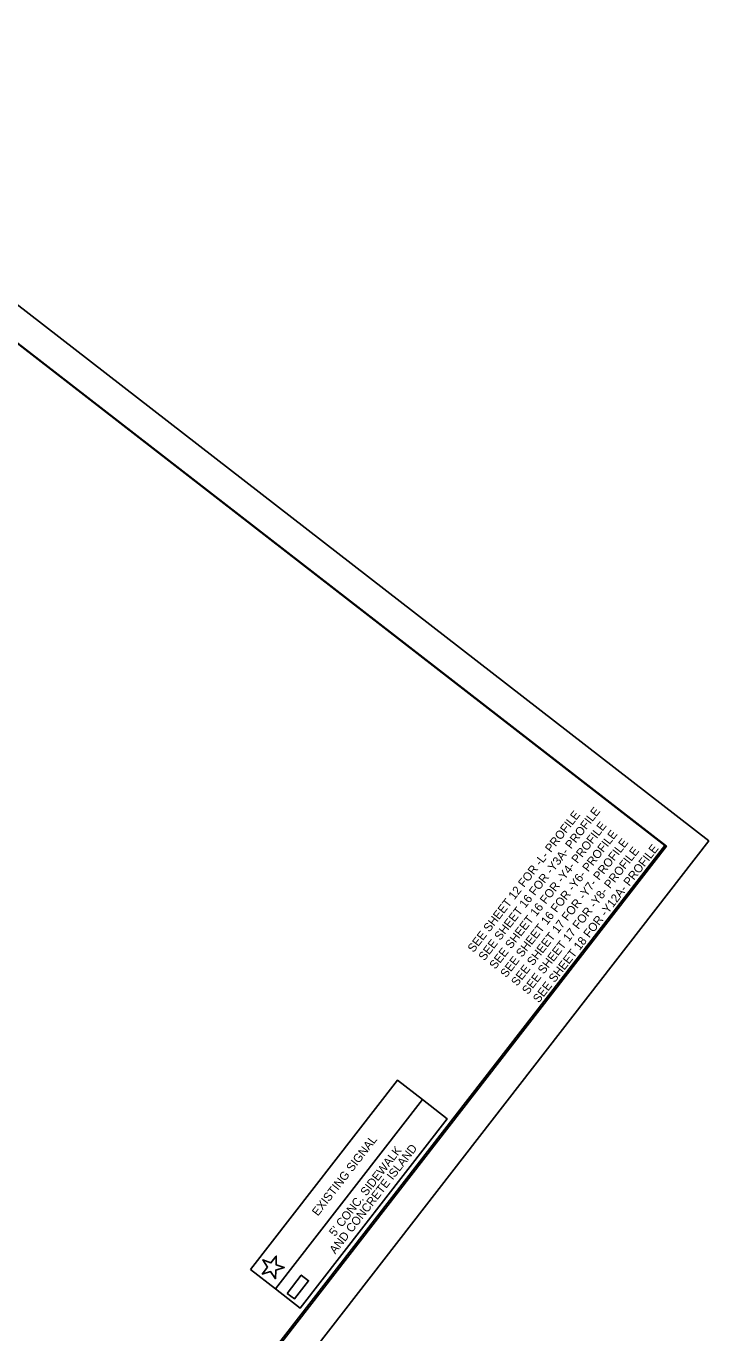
# Model space of a CAD drawing. Extents: x 2013373 to 2015284, y 444589 to 446636.
# Drawn here: x 2014719 to 2015284, y 445554 to 446636 of the extents above; entities that cross this region are included whole.
import ezdxf

# ---------------------------------------------------------------- set-up
doc = ezdxf.new("R2010")
doc.units = 0
for name, color, linetype in [('Old_Level_1', 7, 'Continuous'), ('Prop DSN Text', 7, 'Continuous'), ('Prop RDY Traffic Signal CELL', 7, 'Continuous'), ('Prop Shade Medium', 7, 'Continuous'), ('Sheet Clip Boundary CELL', 7, 'Continuous'), ('Sheet Plan And Profile CELL', 7, 'Continuous'), ('Sheet Plot Border Outside CELL', 7, 'Continuous')]:
    doc.layers.add(name, color=color, linetype=linetype)

msp = doc.modelspace()

# ---------------------------------------------------------------- linework, layer by layer
at = {"layer": 'Old_Level_1'}
for points in [[(2014904.7, 445606.9), (2015026.2, 445763.5), (2015046.8, 445747.5), (2014925.3, 445590.9)], [(2014925.3, 445590.9), (2015046.8, 445747.5), (2015067.4, 445731.5), (2014945.9, 445574.9)]]:
    msp.add_lwpolyline(points, close=True, dxfattribs=at)
at = {"layer": 'Prop RDY Traffic Signal CELL'}
msp.add_lwpolyline([(2014918.8, 445608.8), (2014914.4, 445603.1), (2014921.3, 445605.1), (2014925.4, 445599.2), (2014925.6, 445606.4), (2014932.6, 445608.4), (2014925.8, 445610.8), (2014926, 445618), (2014921.6, 445612.3), (2014914.8, 445614.8), (2014918.8, 445608.8)], dxfattribs=at)
at = {"layer": 'Prop Shade Medium'}
msp.add_lwpolyline([(2014935, 445587.1), (2014946.7, 445602.2), (2014952.7, 445597.5), (2014941, 445582.5)], close=True, dxfattribs=at)
at = {"layer": 'Sheet Clip Boundary CELL'}
msp.add_lwpolyline([(2014175.9, 446280.2), (2013513.1, 445427.6), (2013603.8, 445375.4), (2013612.4, 445329.9), (2013915.8, 445258.4), (2014042, 445083.4), (2014361.1, 444814.9), (2015247.4, 445957.7), (2014564.2, 446487.4), (2014441.6, 446328.9), (2014350.6, 446399.7), (2014226.8, 446240.6)], close=True, dxfattribs=at)
at = {"layer": 'Sheet Plan And Profile CELL'}
msp.add_lwpolyline([(2014418.9, 446600.4), (2013499.7, 445415.1), (2014329.4, 444771.6), (2015248.7, 445957)], close=True, dxfattribs=at)
at = {"layer": 'Sheet Plot Border Outside CELL'}
msp.add_lwpolyline([(2014241.9, 444618), (2015283.7, 445961.4), (2014414.5, 446635.5), (2013372.7, 445292.2)], close=True, dxfattribs=at)

# ---------------------------------------------------------------- texts
at = {"layer": 'Prop DSN Text'}
for s, p in [('SEE SHEET 12 FOR -L- PROFILE', (2015089.1, 445868.7)), ('SEE SHEET 16 FOR -Y3A- PROFILE', (2015098.1, 445861.8)), ('SEE SHEET 16 FOR -Y4- PROFILE', (2015107.1, 445854.8)), ('SEE SHEET 16 FOR -Y6- PROFILE', (2015116.1, 445847.8)), ('SEE SHEET 17 FOR -Y7- PROFILE', (2015125.1, 445840.8)), ('SEE SHEET 18 FOR -Y12A- PROFILE', (2015143.1, 445826.9)), ('SEE SHEET 17 FOR -Y8- PROFILE', (2015134.1, 445833.9)), ('EXISTING SIGNAL', (2014960.4, 445650.6)), ("5' CONC. SIDEWALK", (2014974.5, 445633.7)), ('AND CONCRETE ISLAND', (2014974.8, 445619.2))]:
    msp.add_text(s, height=7, rotation=52.2051, dxfattribs=at).set_placement(p)

doc.saveas('drawing.dxf')
